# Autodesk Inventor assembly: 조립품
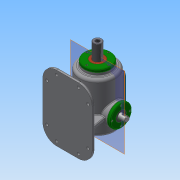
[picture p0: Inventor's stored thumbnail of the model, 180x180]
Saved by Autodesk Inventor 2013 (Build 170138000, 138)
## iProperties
Created: 2019-10
Part Number: 조립품
Document SubType Name: Assembly
Designer: Administrator
Mass: 4941.33 g
Surface Area: 4928.07 cm^2
Volume: 2176.15 cm^3
Density: 2.27067 g/cm^3
Author: Administrator
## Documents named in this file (17)
- C:\Users\Administrator\Desktop\뜸부기\391004V1039\조립품.iam
- C:\Users\Administrator\Desktop\뜸부기\391004V1039\본체.ipt
- C:\Users\Administrator\Desktop\뜸부기\391004V1039\가변스프링.ipt
- C:\Users\Administrator\Desktop\뜸부기\391004V1039\개스킷 A.ipt
- C:\Users\Administrator\Desktop\뜸부기\391004V1039\개스킷 B.ipt
- C:\Users\Administrator\Desktop\뜸부기\391004V1039\고정플레이트.ipt
- C:\Users\Administrator\Desktop\뜸부기\391004V1039\베어링 6205.ipt
- 베어링 6205.ipt
- C:\Users\Administrator\Desktop\뜸부기\391004V1039\볼트 M4x0.7.ipt
- C:\Users\Administrator\Desktop\뜸부기\391004V1039\부시.ipt
- C:\Users\Administrator\Desktop\뜸부기\391004V1039\상부커버.ipt
- C:\Users\Administrator\Desktop\뜸부기\391004V1039\슬라이드 커버.ipt
- C:\Users\Administrator\Desktop\뜸부기\391004V1039\슬라이드.ipt
- C:\Users\Administrator\Desktop\뜸부기\391004V1039\오일 실 25 38 8.ipt
- C:\Users\Administrator\Desktop\뜸부기\391004V1039\육각머리볼트 M4.ipt
- C:\Users\Administrator\Desktop\뜸부기\391004V1039\축 커버.ipt
- C:\Users\Administrator\Desktop\뜸부기\391004V1039\편심축.ipt
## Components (17 placed, 5 different names)
1. 개스킷 A:1
2. 개스킷 B:1
3. 고정플레이트:1 — 플러쉬:57
4. 개스킷 B:2
5. 가변스프링:1
6. M4x0.7:1
7. M4x0.7:4
8. M4x0.7:5
9. M4x0.7:6
10. M4x0.7:2
11. M4x0.7:7
12. M4x0.7:8
13. M4x0.7:9
14. M4x0.7:3
15. M4x0.7:10
16. M4x0.7:11
17. M4x0.7:12
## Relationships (1: Flush 1)
- 플러쉬:57 [Flush]: 고정플레이트:1
